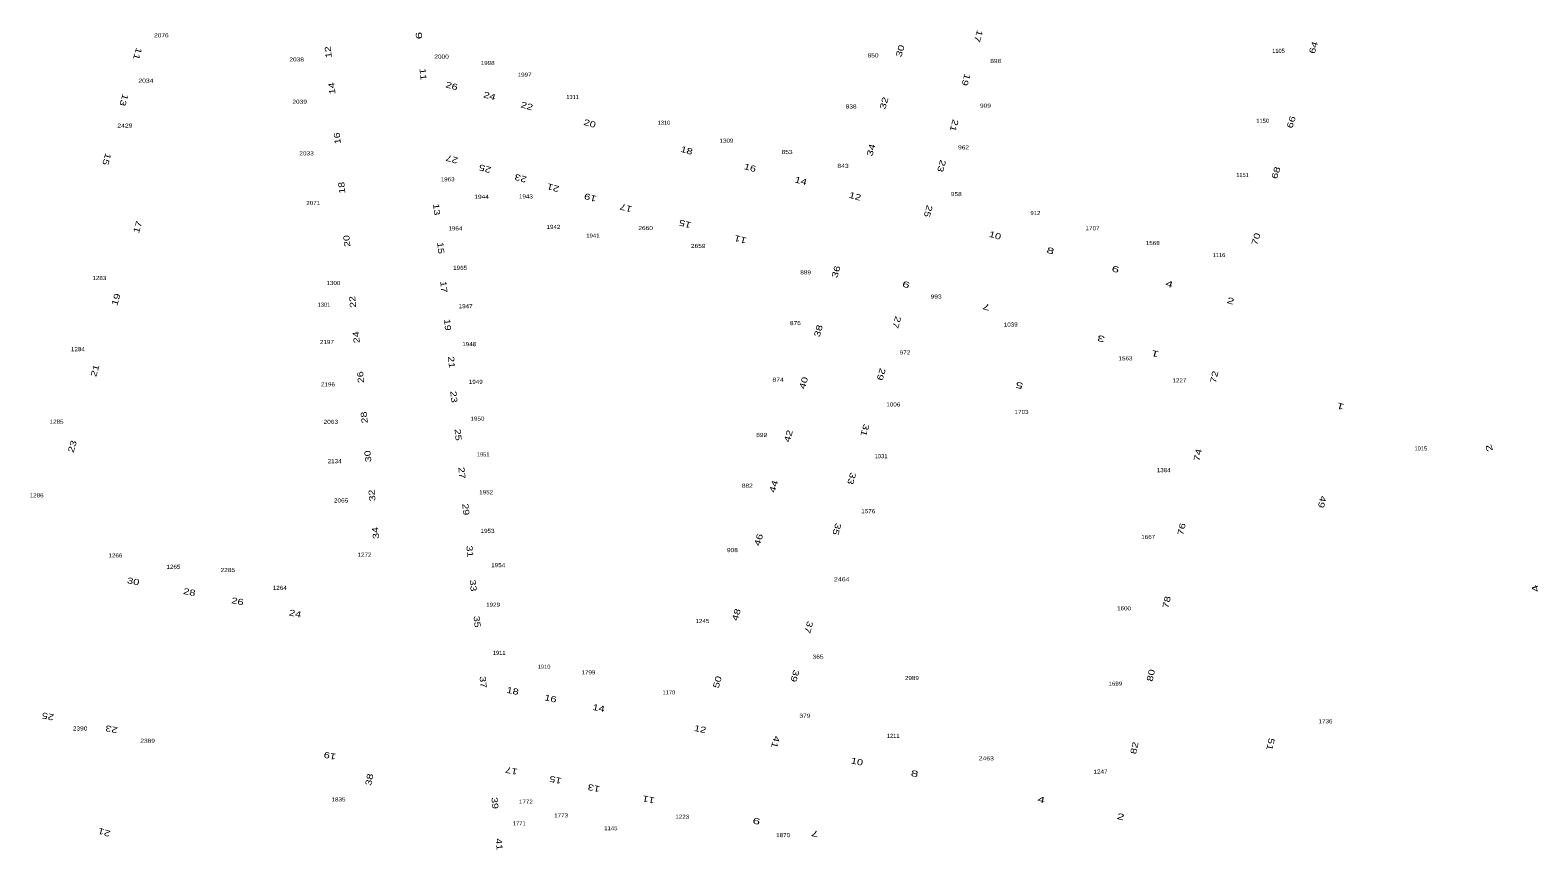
# Model space of a CAD drawing. Extents: x -828673 to -815583, y -1077737 to -1063807.
# Drawn here: x -823378.6 to -823008.1, y -1070860.3 to -1070658.9 of the extents above; entities that cross this region are included whole.
import ezdxf
from ezdxf.enums import TextEntityAlignment as Align

# ---------------------------------------------------------------- set-up
doc = ezdxf.new("R2010")
doc.units = 0
doc.header["$LTSCALE"] = 0.4
doc.layers.add('1', color=7, linetype='Continuous')
doc.layers.add('2', color=7, linetype='Continuous')

msp = doc.modelspace()

# ---------------------------------------------------------------- texts
at = {"layer": '1'}
for s, width, p in [('2076', 1.2, (-823346.331, -1070660.613)), ('1105', 1.05, (-823071.833, -1070664.442)), ('2038', 1.2, (-823313.09, -1070666.542)), ('2000', 1.2, (-823277.482, -1070665.851)), ('1998', 1.15, (-823266.155, -1070667.425)), ('850', 1.2, (-823171.451, -1070665.554)), ('898', 1.2, (-823141.319, -1070666.937)), ('2034', 1.25, (-823350.123, -1070671.764)), ('1997', 1.15, (-823257.083, -1070670.31)), ('2039', 1.2, (-823312.351, -1070676.947)), ('838', 1.2, (-823176.837, -1070678.112)), ('909', 1.2, (-823143.829, -1070677.915)), ('2429', 1.25, (-823355.297, -1070682.803)), ('1310', 1.05, (-823222.827, -1070682.099)), ('1150', 1.05, (-823075.725, -1070681.63)), ('1309', 1.15, (-823207.462, -1070686.507)), ('2033', 1.2, (-823310.662, -1070689.622)), ('853', 1.2, (-823192.569, -1070689.287)), ('962', 1.2, (-823149.215, -1070688.163)), ('843', 1.25, (-823178.829, -1070692.698)), ('1963', 1.15, (-823275.984, -1070695.998)), ('2071', 1.15, (-823309.025, -1070701.822)), ('1944', 1.2, (-823267.651, -1070700.294)), ('1943', 1.15, (-823256.747, -1070700.21)), ('958', 1.2, (-823150.996, -1070699.642)), ('912', 1.1, (-823131.561, -1070704.301)), ('1964', 1.15, (-823274.089, -1070708.066)), ('1942', 1.15, (-823249.989, -1070707.696)), ('2660', 1.2, (-823227.342, -1070707.991)), ('1707', 1.15, (-823117.512, -1070708.028)), ('1941', 1.1, (-823240.307, -1070709.844)), ('2659', 1.2, (-823214.419, -1070712.371)), ('1568', 1.15, (-823102.721, -1070711.664)), ('1283', 1.15, (-823361.574, -1070720.258)), ('1965', 1.15, (-823272.911, -1070717.753)), ('889', 1.2, (-823188.01, -1070718.873)), ('1300', 1.15, (-823304.067, -1070721.468)), ('1301', 1.05, (-823306.39, -1070726.803)), ('1947', 1.15, (-823271.564, -1070727.186)), ('993', 1.2, (-823155.948, -1070724.817)), ('876', 1.2, (-823190.542, -1070731.348)), ('1039', 1.15, (-823137.623, -1070731.694)), ('1284', 1.15, (-823366.853, -1070737.739)), ('2197', 1.15, (-823305.651, -1070735.992)), ('1948', 1.15, (-823270.676, -1070736.506)), ('972', 1.2, (-823163.601, -1070738.55)), ('1563', 1.15, (-823109.418, -1070739.99)), ('2196', 1.15, (-823305.387, -1070746.397)), ('1949', 1.15, (-823269.076, -1070745.771)), ('874', 1.25, (-823194.781, -1070745.252)), ('1227', 1.15, (-823096.178, -1070745.418)), ('1006', 1.15, (-823166.473, -1070751.328)), ('1703', 1.15, (-823134.951, -1070753.164)), ('1285', 1.15, (-823372.076, -1070755.57)), ('2063', 1.2, (-823304.701, -1070755.596)), ('1950', 1.15, (-823268.655, -1070754.803)), ('899', 1.2, (-823198.822, -1070758.813)), ('1951', 1.05, (-823267.266, -1070763.605)), ('1031', 1.05, (-823169.466, -1070764.037)), ('1015', 1.05, (-823036.854, -1070762.139)), ('2134', 1.15, (-823303.75, -1070765.261)), ('1384', 1.15, (-823100.027, -1070767.474)), ('882', 1.2, (-823202.352, -1070771.287)), ('1286', 1.15, (-823376.983, -1070773.665)), ('2065', 1.2, (-823302.167, -1070774.926)), ('1952', 1.15, (-823266.508, -1070772.912)), ('1576', 1.15, (-823172.624, -1070777.555)), ('1953', 1.15, (-823266.174, -1070782.392)), ('908', 1.2, (-823206.014, -1070787.122)), ('1667', 1.15, (-823103.833, -1070783.88)), ('1266', 1.15, (-823357.625, -1070788.423)), ('1272', 1.15, (-823296.413, -1070788.235)), ('1954', 1.15, (-823263.565, -1070790.815)), ('1265', 1.15, (-823343.372, -1070791.222)), ('2285', 1.2, (-823330.016, -1070792.014)), ('2464', 1.3, (-823179.137, -1070794.292)), ('1264', 1.15, (-823317.241, -1070796.398)), ('1929', 1.15, (-823264.827, -1070800.544)), ('1600', 1.15, (-823109.776, -1070801.413)), ('1245', 1.15, (-823213.377, -1070804.531)), ('1910', 1.05, (-823252.289, -1070815.772)), ('365', 1.2, (-823184.964, -1070813.311)), ('1799', 1.15, (-823241.387, -1070817.161)), ('2989', 1.15, (-823161.91, -1070818.56)), ('1699', 1.15, (-823111.922, -1070819.926)), ('1170', 1.05, (-823221.626, -1070822.078)), ('379', 1.2, (-823188.204, -1070827.814)), ('2390', 1.2, (-823366.301, -1070830.953)), ('1736', 1.15, (-823060.27, -1070829.179)), ('2389', 1.2, (-823349.71, -1070833.962)), ('2463', 1.25, (-823143.618, -1070838.291)), ('1247', 1.15, (-823115.558, -1070841.532)), ('1835', 1.15, (-823302.802, -1070848.378)), ('1772', 1.15, (-823256.759, -1070848.929)), ('1773', 1.15, (-823248.103, -1070852.309)), ('1223', 1.15, (-823218.33, -1070852.634)), ('1771', 1.05, (-823258.386, -1070854.255)), ('1145', 1.1, (-823235.886, -1070855.457)), ('1870', 1.15, (-823193.54, -1070857.154))]:
    msp.add_text(s, height=1, dxfattribs=dict(at, width=width)).set_placement(p, align=Align.CENTER)
for s, p in [('1311', (-823245.284, -1070675.767)), ('1151', (-823080.664, -1070694.958)), ('1116', (-823086.443, -1070714.624)), ('1911', (-823263.318, -1070812.36)), ('1211', (-823166.501, -1070832.756))]:
    msp.add_text(s, height=1, dxfattribs=at).set_placement(p, align=Align.CENTER)
at = {"layer": '2'}
for s, rotation, width, p in [('9', 275.37, 1.6, (-823283.7865, -1070660.2573)), ('17', 253.653, 1.35, (-823146.2576, -1070660.1049)), ('11', 253.379, 1.35, (-823352.8897, -1070664.4255)), ('12', 95.65, 1.3, (-823304.5884, -1070664.1843)), ('30', 73.789, 1.35, (-823164.0799, -1070664.1664)), ('64', 73.148, 1.35, (-823062.5164, -1070663.3519)), ('11', 275.897, 1.3, (-823282.7522, -1070669.7609)), ('19', 254.096, 1.35, (-823149.3183, -1070670.8465)), ('13', 253.863, 1.35, (-823356.2354, -1070675.8105)), ('14', 95.857, 1.3, (-823303.6927, -1070673.109)), ('26', 344.611, 1.35, (-823275.1745, -1070673.2681)), ('24', 344.666, 1.35, (-823265.8933, -1070675.7347)), ('22', 344.236, 1.35, (-823256.7158, -1070678.2027)), ('32', 73.85, 1.35, (-823168.0485, -1070676.9881)), ('20', 344.677, 1.35, (-823241.2462, -1070682.5024)), ('21', 254.13, 1.35, (-823152.2323, -1070682.0664)), ('66', 73.128, 1.35, (-823067.9869, -1070681.6742)), ('16', 95.679, 1.3, (-823302.3711, -1070685.3617)), ('15', 253.443, 1.35, (-823360.4632, -1070690.3343)), ('27', 164.536, 1.35, (-823274.732, -1070689.8619)), ('18', 344.676, 1.35, (-823217.4432, -1070689.1104)), ('34', 74.055, 1.35, (-823171.2486, -1070688.5285)), ('25', 164.578, 1.35, (-823266.6076, -1070692.177)), ('16', 344.667, 1.35, (-823201.8683, -1070693.3617)), ('23', 254.133, 1.35, (-823155.3233, -1070692.0314)), ('68', 72.908, 1.35, (-823071.7523, -1070694.1104)), ('18', 95.747, 1.3, (-823301.2638, -1070697.5101)), ('23', 164.646, 1.35, (-823257.8519, -1070694.5357)), ('21', 164.549, 1.35, (-823249.8652, -1070696.8593)), ('14', 344.987, 1.35, (-823189.3868, -1070696.6104)), ('19', 164.832, 1.35, (-823240.7308, -1070699.2625)), ('12', 344.257, 1.35, (-823176.0675, -1070700.3952)), ('13', 275.833, 1.3, (-823279.4259, -1070702.9753)), ('17', 164.543, 1.35, (-823231.9741, -1070701.8281)), ('25', 254.237, 1.35, (-823158.6007, -1070703.1473)), ('17', 73.347, 1.35, (-823351.4465, -1070707.4489)), ('15', 164.591, 1.35, (-823217.4527, -1070705.7453)), ('10', 344.518, 1.35, (-823141.6602, -1070709.9935)), ('20', 95.771, 1.3, (-823300.0285, -1070710.5959)), ('15', 275.962, 1.3, (-823278.4135, -1070712.4521)), ('11', 164.727, 1.35, (-823203.8484, -1070709.5538)), ('70', 73.006, 1.35, (-823076.6459, -1070710.3892)), ('8', 344.492, 1.65, (-823128.06, -1070713.7771)), ('36', 73.84, 1.35, (-823179.8442, -1070718.4202)), ('6', 344.515, 1.65, (-823112.0692, -1070718.3126)), ('17', 275.621, 1.3, (-823277.6604, -1070722.0105)), ('9', 164.588, 1.65, (-823163.1317, -1070720.6494)), ('4', 344.177, 1.65, (-823098.857, -1070721.9501)), ('19', 73.455, 1.35, (-823356.7802, -1070725.2461)), ('22', 95.692, 1.3, (-823298.6025, -1070725.5414)), ('7', 164.631, 1.65, (-823143.3897, -1070726.1501)), ('2', 344.653, 1.65, (-823083.7945, -1070726.0795)), ('19', 275.469, 1.3, (-823276.7303, -1070731.3305)), ('27', 254.221, 1.35, (-823166.3472, -1070730.4275)), ('24', 95.752, 1.3, (-823297.706, -1070734.2572)), ('38', 74.27, 1.35, (-823184.1822, -1070732.9498)), ('3', 164.553, 1.65, (-823115.2242, -1070733.9579)), ('1', 165.175, 1.65, (-823101.9481, -1070737.6668)), ('21', 73.752, 1.35, (-823361.9539, -1070742.7223)), ('21', 275.467, 1.3, (-823275.7624, -1070740.5115)), ('26', 95.496, 1.3, (-823296.6494, -1070744.0803)), ('40', 73.82, 1.35, (-823187.8006, -1070745.748)), ('29', 254.017, 1.35, (-823170.1545, -1070743.2285)), ('5', 164.101, 1.65, (-823135.2905, -1070745.4278)), ('72', 77.762, 1.35, (-823086.89, -1070744.2245)), ('23', 275.894, 1.3, (-823275.1953, -1070749.038)), ('28', 95.811, 1.3, (-823295.7515, -1070753.9639)), ('1', 163.662, 1.65, (-823056.383, -1070750.5658)), ('31', 254.075, 1.35, (-823174.1519, -1070756.9107)), ('23', 73.61, 1.35, (-823367.5082, -1070761.3601)), ('25', 275.289, 1.3, (-823274.145, -1070758.3449)), ('42', 74.095, 1.35, (-823191.5487, -1070758.8035)), ('30', 95.67, 1.3, (-823294.8569, -1070763.5006)), ('74', 78.001, 1.35, (-823090.943, -1070763.4039)), ('2', 108.704, 1.65, (-823019.3589, -1070761.306)), ('27', 275.864, 1.3, (-823273.2171, -1070767.7199)), ('33', 254.096, 1.35, (-823177.4023, -1070768.8185)), ('44', 74.055, 1.35, (-823195.1636, -1070771.1925)), ('32', 95.438, 1.3, (-823293.8518, -1070773.1126)), ('49', 257.707, 1.35, (-823061.8275, -1070774.6198)), ('29', 275.989, 1.3, (-823272.2478, -1070776.6902)), ('34', 95.848, 1.3, (-823292.9575, -1070782.3549)), ('35', 253.621, 1.35, (-823181.0495, -1070781.244)), ('76', 77.842, 1.35, (-823094.9059, -1070781.6275)), ('31', 275.595, 1.3, (-823271.2571, -1070787.0114)), ('46', 73.634, 1.35, (-823198.8648, -1070784.2898)), ('30', 348.745, 1.35, (-823353.3814, -1070795.0287)), ('28', 348.754, 1.35, (-823339.5748, -1070797.6643)), ('33', 275.76, 1.3, (-823270.4398, -1070795.3922)), ('4', 107.941, 1.65, (-823008.0299, -1070795.854)), ('26', 349.129, 1.35, (-823327.749, -1070799.9348)), ('78', 77.9, 1.35, (-823098.5865, -1070799.5707)), ('24', 348.461, 1.35, (-823313.6015, -1070802.948)), ('35', 275.635, 1.3, (-823269.473, -1070804.2784)), ('48', 73.915, 1.35, (-823204.334, -1070802.7103)), ('37', 254.047, 1.35, (-823187.9646, -1070805.3534)), ('37', 275.233, 1.3, (-823268.0074, -1070819.1271)), ('50', 74.07, 1.35, (-823209.0069, -1070819.2464)), ('39', 253.603, 1.35, (-823191.365, -1070817.3238)), ('80', 77.921, 1.35, (-823102.473, -1070817.5574)), ('18', 348.526, 1.35, (-823260.1552, -1070821.9393)), ('16', 348.197, 1.35, (-823250.8534, -1070823.7958)), ('25', 168.774, 1.35, (-823374.082, -1070826.763)), ('14', 348.569, 1.35, (-823239.0236, -1070826.1513)), ('23', 168.707, 1.35, (-823358.4316, -1070829.9143)), ('12', 348.248, 1.35, (-823214.0853, -1070831.3225)), ('41', 253.684, 1.35, (-823196.1269, -1070833.5453)), ('82', 77.919, 1.35, (-823106.513, -1070835.3965)), ('51', 257.482, 1.35, (-823074.5044, -1070834.1399)), ('19', 168.67, 1.35, (-823304.7692, -1070836.4264)), ('10', 348.157, 1.35, (-823175.5469, -1070839.3038)), ('38', 78.646, 1.35, (-823294.5208, -1070843.1557)), ('17', 168.415, 1.35, (-823260.1594, -1070840.1188)), ('8', 348.324, 1.65, (-823161.3808, -1070842.2817)), ('15', 167.657, 1.35, (-823249.3267, -1070842.3552)), ('13', 168.457, 1.35, (-823239.9104, -1070844.3769)), ('39', 276.06, 1.3, (-823265.106, -1070848.8528)), ('11', 168.444, 1.35, (-823226.4588, -1070847.1845)), ('4', 348.286, 1.65, (-823130.2783, -1070848.6672)), ('9', 168.248, 1.65, (-823199.9477, -1070852.4932)), ('2', 347.602, 1.65, (-823110.761, -1070852.8463)), ('21', 163.689, 1.35, (-823360.1809, -1070855.2544)), ('7', 168.222, 1.65, (-823185.5759, -1070855.5567)), ('41', 275.65, 1.3, (-823264.0466, -1070858.9557))]:
    msp.add_text(s, height=1.5, rotation=rotation, dxfattribs=dict(at, width=width)).set_placement(p, align=Align.CENTER)

doc.saveas('drawing.dxf')
